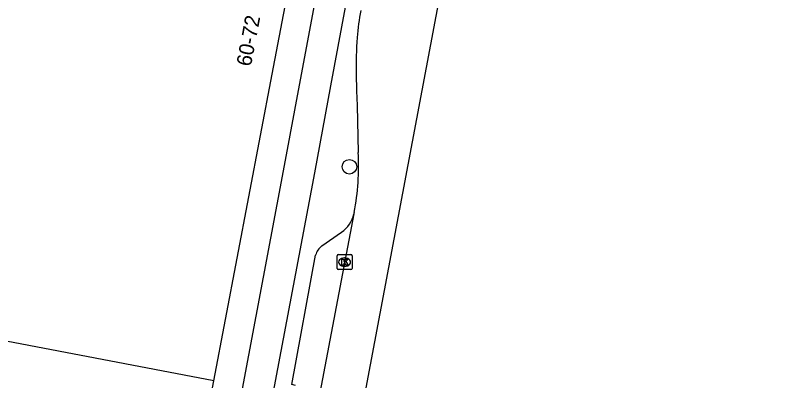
# Model space of a CAD drawing. Extents: x 161402 to 161933, y 381650 to 382313.
# Drawn here: x 161861.5 to 161912, y 381882.3 to 381906.8 of the extents above; entities that cross this region are included whole.
import ezdxf

# ---------------------------------------------------------------- set-up
doc = ezdxf.new("R2010")
doc.units = 0
for name, color, linetype in [('IMGEO_Boom', 7, 'Continuous'), ('IMGEO_Fietspad_gesloten', 7, 'Continuous'), ('IMGEO_Kolk', 7, 'Continuous'), ('IMGEO_OVBaan_gesloten', 7, 'Continuous'), ('IMGEO_Pand', 7, 'Continuous'), ('IMGEO_Pand_nummerreeks', 7, 'Continuous'), ('IMGEO_Parkeervlak_open', 7, 'Continuous'), ('IMGEO_Rijbaan_lokaal_gesloten', 7, 'Continuous')]:
    doc.layers.add(name, color=color, linetype=linetype)

msp = doc.modelspace()

# ---------------------------------------------------------------- linework, layer by layer
at = {"layer": 'IMGEO_Boom'}
msp.add_circle((161883.862, 381896.668), 0.489, dxfattribs=at)
at = {"layer": 'IMGEO_Fietspad_gesloten'}
for points in [[(161869.899, 381834.602), (161881.54, 381896.271), (161882.623, 381902.093), (161888.398, 381933.147), (161890.059, 381942.083), (161900.83, 382000), (161908.061, 382038.88), (161912.039, 382060.567)], [(161886.669, 381935.154), (161880.56, 381902.497), (161879.486, 381896.758), (161857.65, 381780.798), (161851.928, 381750), (161842.232, 381697.819)]]:
    msp.add_lwpolyline(points, dxfattribs=at)
at = {"layer": 'IMGEO_Kolk'}
for p, q in [((161883.036, 381889.853), (161883.036, 381890.705)), ((161883.111, 381890.779), (161883.963, 381890.779)), ((161884.037, 381890.705), (161884.037, 381889.853)), ((161883.524, 381890.559), (161883.549, 381890.559)), ((161883.963, 381889.779), (161883.111, 381889.779)), ((161883.547, 381889.999), (161883.522, 381889.999))]:
    msp.add_line(p, q, dxfattribs=at)
for points in [[(161883.036, 381889.853), (161883.036, 381890.705)], [(161883.111, 381890.779), (161883.963, 381890.779)], [(161884.037, 381890.705), (161884.037, 381889.853)], [(161883.357, 381890.479), (161883.48, 381890.479), (161883.48, 381890.328), (161883.61, 381890.479), (161883.774, 381890.479), (161883.628, 381890.328), (161883.781, 381890.079), (161883.629, 381890.079), (161883.544, 381890.243), (161883.48, 381890.176), (161883.48, 381890.079), (161883.357, 381890.079), (161883.357, 381890.479)], [(161883.963, 381889.779), (161883.111, 381889.779)]]:
    msp.add_lwpolyline(points, dxfattribs=at)
for centre, start, end in [((161883.113, 381890.703), 91.552, 178.448), ((161883.113, 381890.703), 91.552, 178.448), ((161883.961, 381890.703), 1.552, 88.448), ((161883.961, 381890.703), 1.552, 88.448), ((161883.113, 381889.855), 181.552, 268.448), ((161883.113, 381889.855), 181.552, 268.448), ((161883.961, 381889.855), 271.552, 358.448), ((161883.961, 381889.855), 271.552, 358.448)]:
    msp.add_arc(centre, 0.0765, start, end, dxfattribs=at)
for centre, major_axis, ratio, start_param, end_param in [((161883.523, 381890.279), (-0.387, 0.002), 0.722429, 4.712389, 7.853982), ((161883.548, 381890.279), (-0.39, 0.002), 0.717154, 1.570796, 4.712389)]:
    msp.add_ellipse(centre, major_axis=major_axis, ratio=ratio, start_param=start_param, end_param=end_param, dxfattribs=at)
at = {"layer": 'IMGEO_OVBaan_gesloten'}
msp.add_lwpolyline([(161866.208, 381782.197), (161889.963, 381908.334)], dxfattribs=at)
at = {"layer": 'IMGEO_Pand'}
for points in [[(161874.777, 381882.317), (161878.687, 381902.863), (161883.878, 381930.136)], [(161874.777, 381882.317), (161856.391, 381885.835)], [(161872.114, 381868.466), (161874.777, 381882.317)]]:
    msp.add_lwpolyline(points, dxfattribs=at)
at = {"layer": 'IMGEO_Parkeervlak_open'}
for points in [[(161882.019, 381891.364), (161883.334, 381892.284)], [(161880.247, 381882.004), (161879.995, 381882.07), (161881.594, 381890.733)]]:
    msp.add_lwpolyline(points, dxfattribs=at)
for centre, radius, start, end in [((161882.199, 381893.926), 1.996, 304.6546, 347.792), ((161882.645, 381890.484), 1.08, 125.4179, 166.6589)]:
    msp.add_arc(centre, radius, start, end, dxfattribs=at)
at = {"layer": 'IMGEO_Rijbaan_lokaal_gesloten'}
for points in [[(161884.315, 381902.888), (161884.344, 381901.757), (161884.369, 381900.783), (161884.448, 381897.633)], [(161884.15, 381893.504), (161864.093, 381787.863), (161863.613, 381786.178), (161863.081, 381785.029), (161862.376, 381783.945), (161861.521, 381781.789), (161860.529, 381779.475)], [(161884.17, 381893.607), (161884.15, 381893.504)]]:
    msp.add_lwpolyline(points, dxfattribs=at)
for centre, radius, start, end in [((161905.47, 381903.518), 21.168, 170.1369, 175.0841), ((161905.361, 381903.551), 21.056, 175.1484, 181.8047), ((161868.789, 381896.692), 15.687, 348.6598, 3.4401)]:
    msp.add_arc(centre, radius, start, end, dxfattribs=at)

# ---------------------------------------------------------------- texts
at = {"layer": 'IMGEO_Pand_nummerreeks'}
msp.add_text('60-72', height=1, rotation=79.2235, dxfattribs=at).set_placement((161877.253, 381903.35))

doc.saveas('drawing.dxf')
